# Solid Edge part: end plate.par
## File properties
Author: Binay
Template: sync ansi part.par
Last saved by: CADCIM
Revision: 8
Application: Solid Edge
Accuracy: 0.990
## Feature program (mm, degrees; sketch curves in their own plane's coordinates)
sketch for "unnamed Hole 1" plane through (74.0576, 73.9259, 6.35) normal (0, 0, 1) x-axis (1, 0, 0)
  hole centre (-38.8262, -36.609) bore radius 3.302
hole "unnamed Hole 1" through
pattern "unnamed Pattern 1" of "unnamed Hole 1"
hole "unnamed Hole 2" through
hole "unnamed Hole 3" through
hole "unnamed Hole 4" through
pattern "PatternOccurrence_5"  XCount = 4; XOffset = 90 deg
pattern "unnamed Pattern 3" of "unnamed Hole 1"
pattern "PatternOccurrence_1"  XCount = 2; YCount = 2; XOffset = 76.2 mm; YOffset = 76.2 mm
hole "unnamed Hole 5" through
hole "unnamed Hole 6" through
hole "unnamed Hole 7" through
sketch for "Hole_5" plane through (73.6248, 74.4917, 6.35) normal (0, 0, 1) x-axis (1, 0, 0)
  hole centre (-0.2934, 0.9253) bore radius 12.7
hole "Hole_5" diameter 25.4 through
pattern "unnamed Pattern 4" of "Hole_5"
sketch for "Hole_6" plane through (74.8044, 76.257, 6.35) normal (0, 0, 1) x-axis (1, 0, 0)
  hole centre (-1.4729, 19.7975) bore radius 2.413
hole "Hole_6" diameter 4.826 through
pattern "unnamed Pattern 2" of "Hole_6"
pattern "unnamed Pattern 5" of "Hole_6"
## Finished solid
Body 1: solid body, 15 faces, 30 edges, 8 vertices.
  Faces by surface: cylinder 9, plane 6
  Edges by curve: circle 18, line 12
Bounding box of the edges (mm): 101.600 x 101.600 x 12.700, from (22.5315, 24.617, -6.35) to (124.1315, 126.217, 6.35).
Cylindrical faces by radius (mm): R2.413 x4, R3.302 x4, R12.7 x1
Planar faces by outward normal: +x 1, +y 1, +z 1, -x 1, -y 1, -z 1
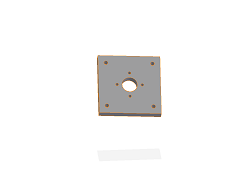
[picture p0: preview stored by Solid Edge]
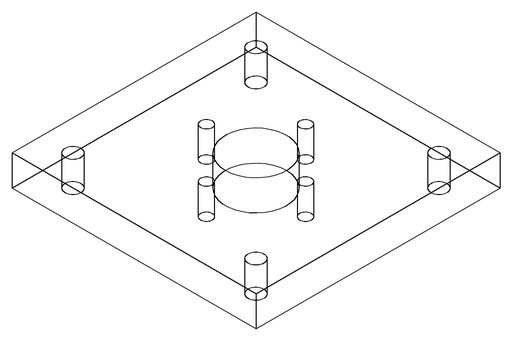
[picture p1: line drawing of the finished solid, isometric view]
